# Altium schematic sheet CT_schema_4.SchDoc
size 352 x 211 mm
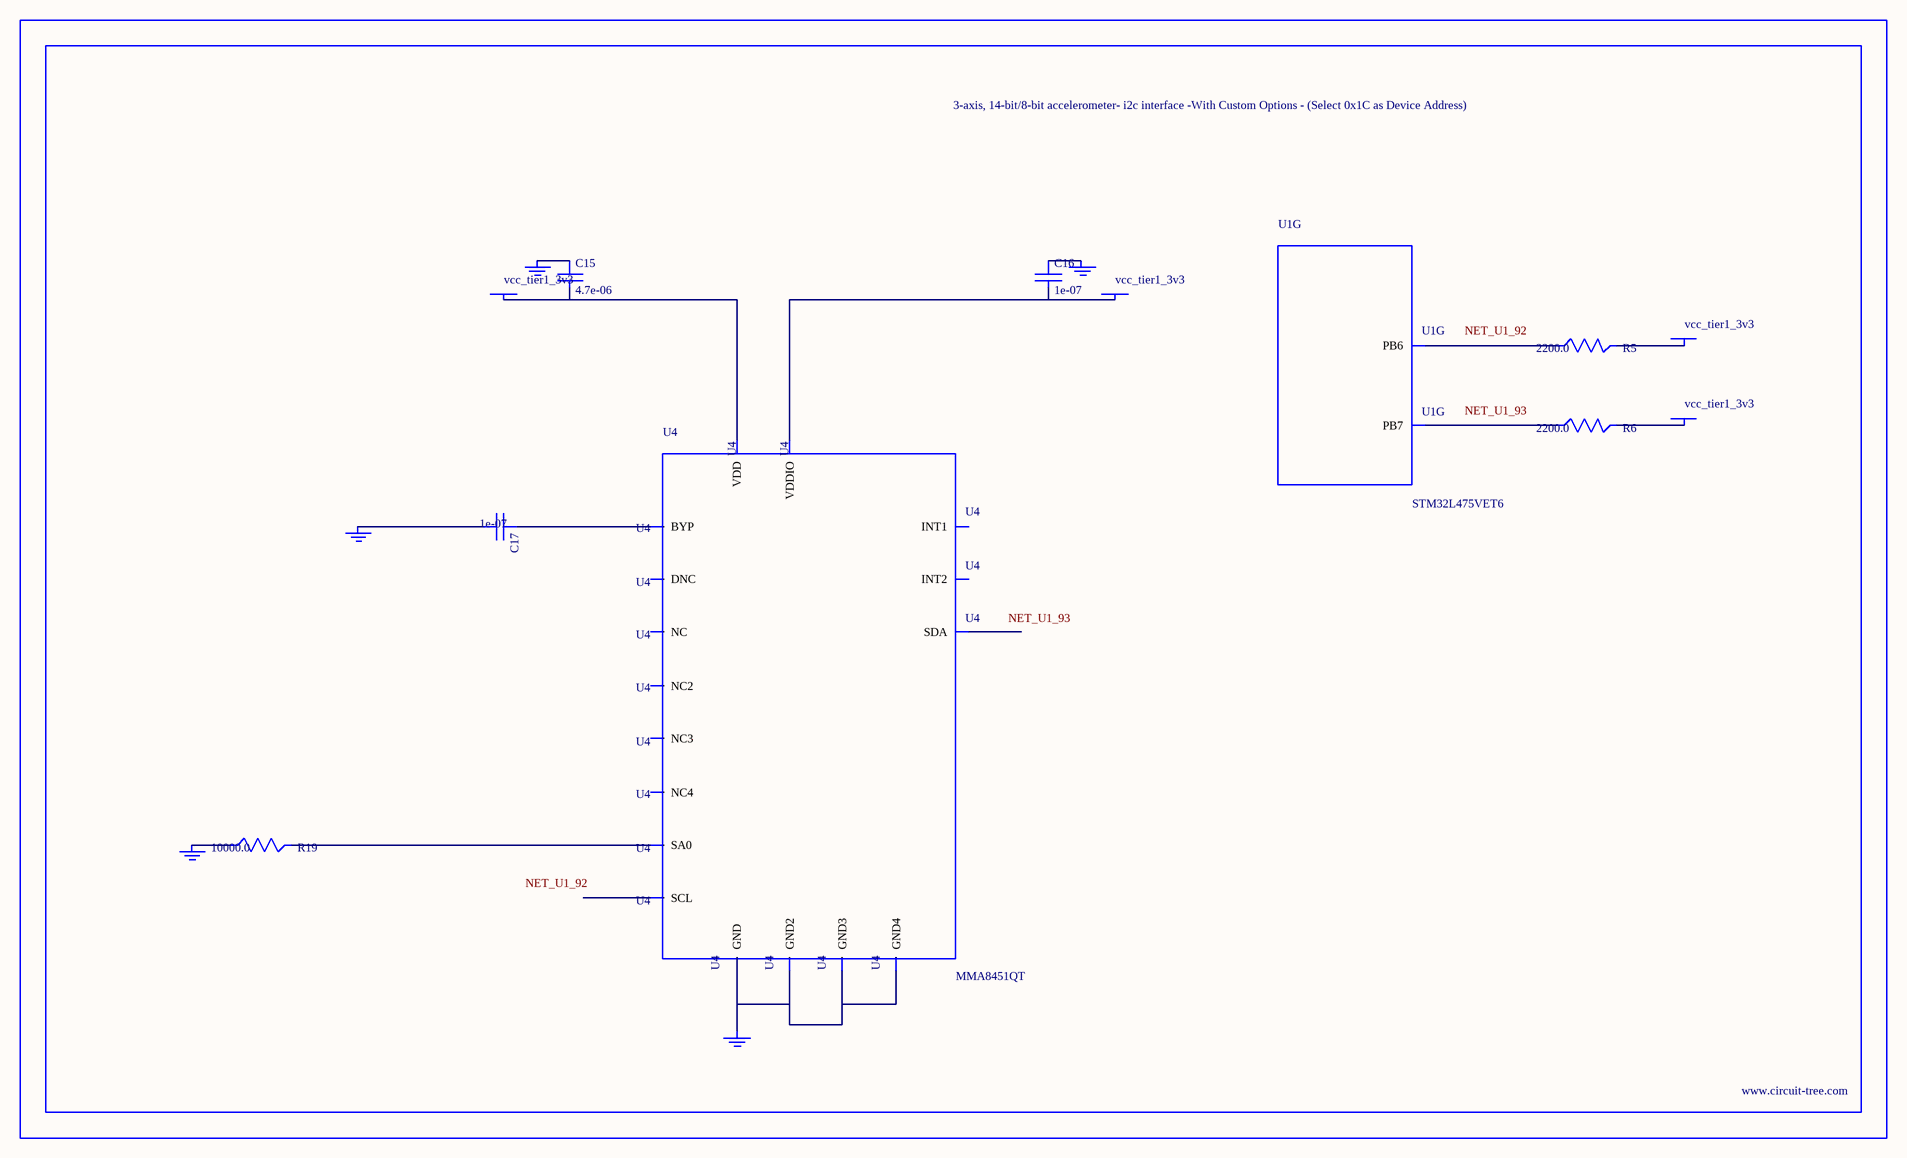
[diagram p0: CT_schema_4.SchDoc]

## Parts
BORDER3  (no value)
C15  4.7e-06  [C0805]
C16  1e-07  [C0402]
C17  1e-07  [C0402]
GND_INSTANCE_3_0  (no value)
GND_INSTANCE_3_1  (no value)
GND_INSTANCE_3_2  (no value)
GND_INSTANCE_3_3  (no value)
GND_INSTANCE_3_4  (no value)
POWER_INSTANCE_3_0  vcc_tier1_3v3
POWER_INSTANCE_3_1  vcc_tier1_3v3
POWER_INSTANCE_3_2  vcc_tier1_3v3
POWER_INSTANCE_3_3  vcc_tier1_3v3
R5  2200.0  [R0603]
R6  2200.0  [R0603]
R19  10000.0  [R0603]
U1  STM32L475VET6  [LQFP100]  (part G of 9)
U4  MMA8451QT  [QFN-16]

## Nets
NetC15_1: C15.1 GND_INSTANCE_3_3.0(GND)
NetC15_2: C15.2 POWER_INSTANCE_3_1.0(PWR) U4.14(VDD)
NetC16_1: C16.1 GND_INSTANCE_3_0.0(GND)
NetC16_2: C16.2 POWER_INSTANCE_3_0.0(PWR) U4.1(VDDIO)
NetC17_1: C17.1 U4.2(BYP)
NetC17_2: C17.2 GND_INSTANCE_3_1.0(GND)
NetGND_INSTANCE_3_2_0: GND_INSTANCE_3_2.0(GND) R19.1
NetGND_INSTANCE_3_4_0: GND_INSTANCE_3_4.0(GND) U4.5(GND) U4.10(GND2) U4.12(GND3) U4.17(GND4)
NetPOWER_INSTANCE_3_2_0: POWER_INSTANCE_3_2.0(PWR) R5.2
NetPOWER_INSTANCE_3_3_0: POWER_INSTANCE_3_3.0(PWR) R6.2
NetR5_1: R5.1 U1.92(PB6)
NetR6_1: R6.1 U1.93(PB7)
NetR19_2: R19.2 U4.7(SA0)

Not connected (* = marked no-connect by the designer): U4 3(DNC) 4(SCL) 6(SDA) 8(NC) 9(INT2) 11(INT1) 13(NC2) 15(NC3) 16(NC4)

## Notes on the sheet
- Labels drawn without touching a wire or pin: NET_U1_92, NET_U1_93

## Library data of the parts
BORDER3 = BORDER_PAGE3
C15 = C0805C475K4RACTU
C16 C17 = C0402C104K3RACTU
GND_INSTANCE_3_0-GND_INSTANCE_3_4 = GND
POWER_INSTANCE_3_0-POWER_INSTANCE_3_3 = PWR
R5 R6 = RC0603JR-072K2L
R19 = RC0603JR-0710KL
